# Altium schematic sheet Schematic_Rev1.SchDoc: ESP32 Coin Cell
size Letter; DrawnBy: x; Engineer: x; Address1: Mike Rankin; Address2: 0miker0@gmail.com; Address3: @mikerankin; DocumentNumber: 1; Revision: 1; SheetNumber: 1; SheetTotal: 1
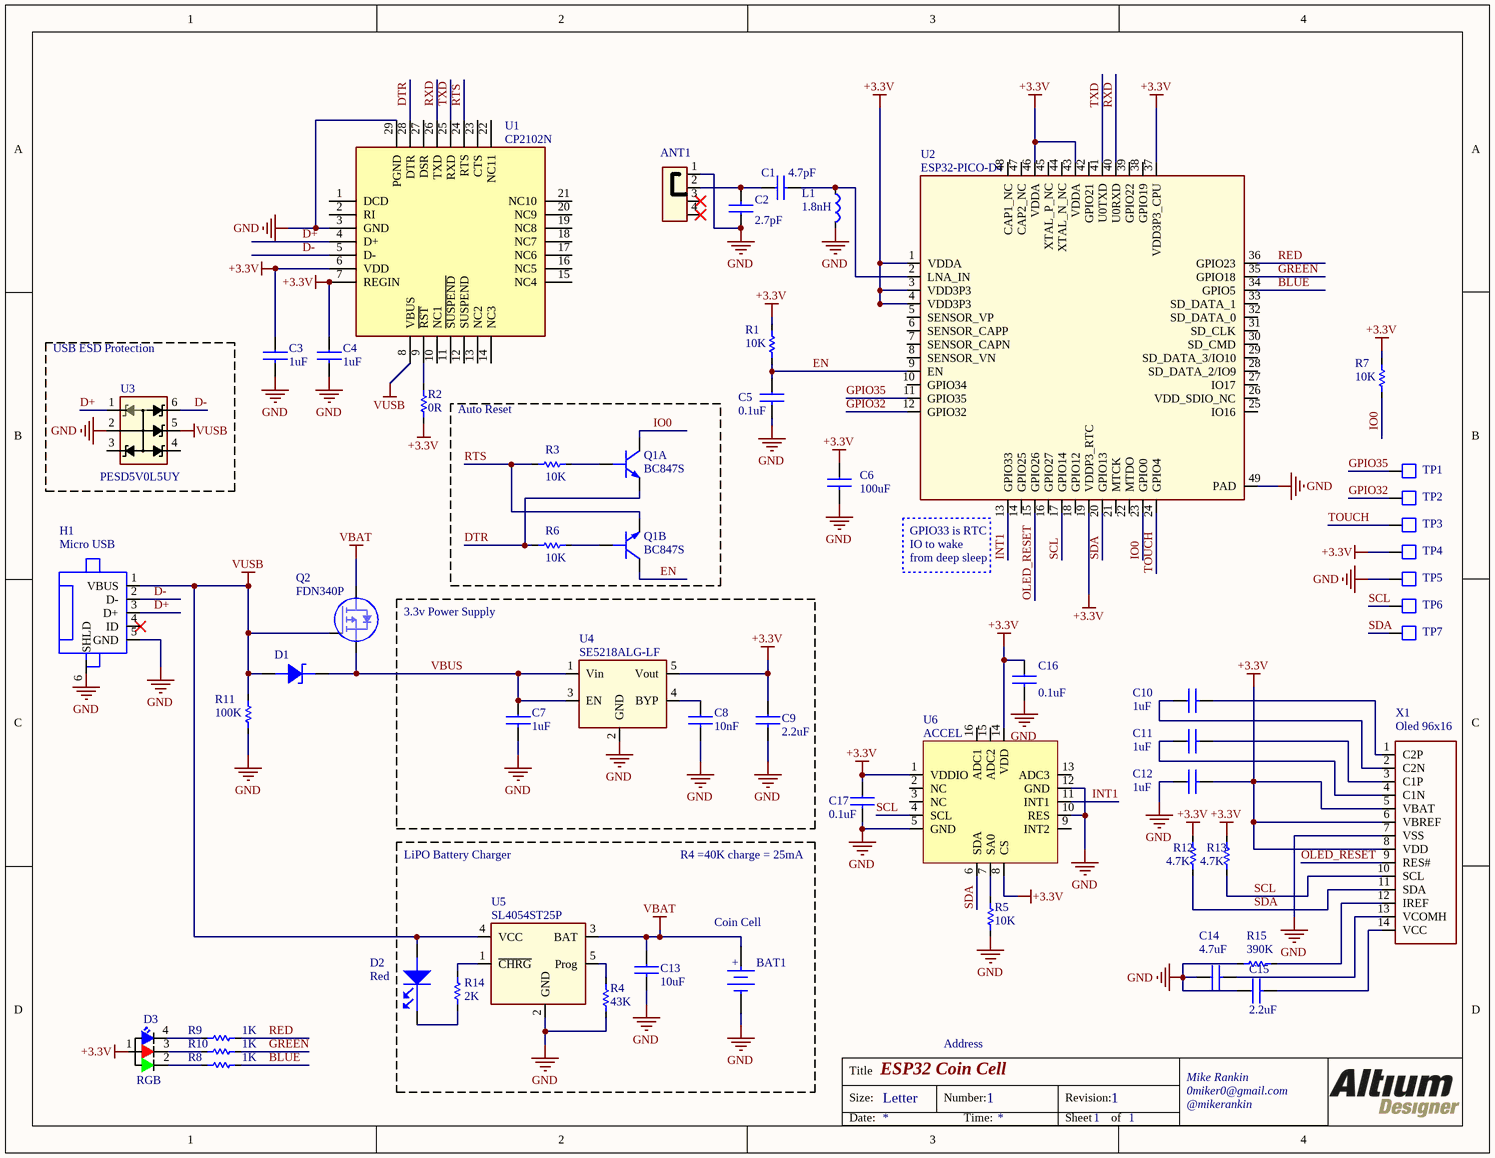
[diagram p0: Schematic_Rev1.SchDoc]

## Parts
ANT1  RF ANT 2.4GHZ STAMPED MET SLD  [PRO-OB-440]  (value not drawn)
BAT1  BATTERY-HOLDER (2450)  [BU2450SM-JJ-GTR]  (value not drawn)
C1  4.7pF  [CAPC1005X56N]
C2  2.7pF  [CAPC1005X56N]
C3  1uF  [CAPC1005X56N]
C4  1uF  [CAPC1005X56N]
C5  0.1uF  [CAPC1005X56N]
C6  100uF  [CAPC3216X160N]
C7  1uF  [CAPC1005X56N]
C8  10nF  [CAPC1005X56N]
C9  2.2uF  [CAPC1005X56N]
C10  1uF  [CAPC1005X56N]
C11  1uF  [CAPC1005X56N]
C12  1uF  [CAPC1005X56N]
C13  10uF  [CAPC2012X140N]
C14  4.7uF  [CAPC1005X56N]
C15  2.2uF  [CAPC1005X56N]
C16  0.1uF  [RESC1005X40L]
C17  0.1uF  [CAPC1005X56N]
D1  MBR0520-TP  [SOD123]  (value not drawn)
D2  value Red  [LED1608X55N-RED]  (hidden comment: LED_0603)
D3  RGB  [FC-B1010RGBT-HG]
H1  Micro USB  [1981584-1]
L1  value 1.8nH  [RESC1005X40L]  (hidden comment: Inductor)
Q1  BC847S  [SOT65P210X110-6N]  (parts A,B of 2)
Q2  FDN340P  [SOT95P240X110-3N]
R1  10K  [RESC1005X40L]
R2  0R  [RESC1005X40L]
R3  10K  [RESC1005X40L]
R4  43K  [RESC1005X40L]
R5  10K  [RESC1005X40L]
R6  10K  [RESC1005X40L]
R7  10K  [RESC1005X40L]
R8  1K  [RESC1005X40L]
R9  1K  [RESC1005X40L]
R10  1K  [RESC1005X40L]
R11  100K  [RESC1005X40L]
R12  4.7K  [RESC1005X40L]
R13  4.7K  [RESC1005X40L]
R14  2K  [RESC1005X40L]
R15  390K  [RESC1005X40L]
TP1  Test Point, 1mm Top Layer  [TP100TL]  (value not drawn)  (no BOM)
TP2  Test Point, 1mm Top Layer  [TP100TL]  (value not drawn)  (no BOM)
TP3  Test Point, 1mm Top Layer  [TP100TL]  (value not drawn)  (no BOM)
TP4  Test Point, 1mm Top Layer  [TP100TL]  (value not drawn)  (no BOM)
TP5  Test Point, 1mm Top Layer  [TP100TL]  (value not drawn)  (no BOM)
TP6  Test Point, 1mm Top Layer  [TP100TL]  (value not drawn)  (no BOM)
TP7  Test Point, 1mm Top Layer  [TP100TL]  (value not drawn)  (no BOM)
U1  CP2102N  [28-QFN]
U2  ESP32-PICO-D4  [QFN48]
U3  PESD5V0L5UY  [SOT65P210X110-6N]
U4  SE5218ALG-LF  [SOT95P280X144-5N]
U5  SL4054ST25P  [SOT95P280X144-5N]
U6  ACCEL  [QFN3X3_16_1.2]
X1  OLED_GLASS 96x16  [OLED_GLASS 96x16]  (value not drawn)

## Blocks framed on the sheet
USB ESD Protection: U3
Auto Reset: Q1 R3 R6
3.3v Power Supply: C7-C9 U4

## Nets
+3.3V: C3.1 C4.1 C6.1 C9.1 C12.2 C16.1 C17.1 D3.1 R1.1 R2.1 R7.1 R12.1 R13.1 TP4.1 U1.6(VDD) U1.7(REGIN) U2.1(VDDA) U2.3(VDD3P3) U2.4(VDD3P3) U2.19(VDDP3_RTC) U2.37(VDD3P3_CPU) U2.43(VDDA) U2.46(VDDA) U4.5(Vout) U6.1(VDDIO) U6.8(CS) U6.14(VDD) X1.5(VBAT) X1.6(VBREF) X1.8(VDD)
GND: ANT1.1 BAT1.2(-) C2.1 C3.2 C4.2 C5.2 C6.2 C7.2 C8.2 C9.2 C12.1 C13.2 C14.1 C15.1 C16.2 C17.2 H1.5(GND) H1.6(SHLD) L1.2 R4.2 R5.2 R11.2 R15.1 TP5.1 U1.3(GND) U1.29(PGND) U2.49(PAD) U3.2 U4.2(GND) U5.2(GND) U6.5(GND) U6.10(RES) U6.12(GND) X1.7(VSS)
VBAT: BAT1.1(+) C13.1 Q2.3(D) U5.3(BAT)
VUSB: D1.2(Annode) D2.2(ANODE) H1.1(VBUS) Q2.1(G) R11.1 U1.8(VBUS) U3.5 U5.4(VCC)
BLUE: R8.2 U2.34(GPIO5)
D+: H1.3(D+) U1.4(D+) U3.1
D-: H1.2(D-) U1.5(D-) U3.6
DTR: Q1.1(E1) R6.2 U1.28(DTR)
EN: C5.1 Q1.3(C2) R1.2 U2.9(EN)
GPIO32: TP2.1 U2.12(GPIO32)
GPIO35: TP1.1 U2.11(GPIO35)
GREEN: R10.2 U2.35(GPIO18)
INT1: U2.13(GPIO33) U6.11(INT1)
IO0: Q1.6(C1) R7.2 U2.23(GPIO0)
OLED_RESET: U2.15(GPIO26) X1.9(RES#)
RED: R9.2 U2.36(GPIO23)
RTS: Q1.4(E2) R3.2 U1.24(RTS)
RXD: U1.26(TXD) U2.40(U0RXD)
SCL: R13.2 TP6.1 U2.17(GPIO14) U6.4(SCL) X1.10(SCL)
SDA: R12.2 TP7.1 U2.20(GPIO13) U6.6(SDA) X1.11(SDA)
TOUCH: TP3.1 U2.24(GPIO4)
TXD: U1.25(RXD) U2.41(U0TXD)
VBUS: C7.1 D1.1(Cathode) Q2.2(S) U4.1(Vin) U4.3(EN)
NetANT1_2: ANT1.2 C1.1 C2.2
NetC1_2: C1.2 L1.1 U2.2(LNA_IN)
NetC8_1: C8.1 U4.4(BYP)
NetC10_1: C10.1 X1.2(C2N)
NetC10_2: C10.2 X1.1(C2P)
NetC11_1: C11.1 X1.4(C1N)
NetC11_2: C11.2 X1.3(C1P)
NetC14_2: C14.2 X1.13(VCOMH)
NetC15_2: C15.2 X1.14(VCC)
NetD2_1: D2.1(CATHODE) R14.1
NetD3_2: D3.2 R8.1
NetD3_3: D3.3 R10.1
NetD3_4: D3.4 R9.1
NetQ1_2: Q1.2(B1) R3.1
NetQ1_5: Q1.5(B2) R6.1
NetR2_2: R2.2 U1.9(~{RST})
NetR4_1: R4.1 U5.5(Prog)
NetR5_1: R5.1 U6.7(SA0)
NetR14_2: R14.2 U5.1(~{CHRG})
NetR15_2: R15.2 X1.12(IREF)

Not connected (* = marked no-connect by the designer): ANT1 3* 4*; H1 4(ID)*; U1 1(DCD) 2(RI) 10(NC1) 11(~{SUSPEND}) 12(SUSPEND) 13(NC2) 14(NC3) 15(NC4) 16(NC5) 17(NC6) 18(NC7) 19(NC8) 20(NC9) 21(NC10) 22(NC11) 23(CTS) 27(DSR); U2 5(SENSOR_VP) 6(SENSOR_CAPP) 7(SENSOR_CAPN) 8(SENSOR_VN) 10(GPIO34) 14(GPIO25) 16(GPIO27) 18(GPIO12) 21(MTCK) 22(MTDO) 25(IO16) 26(VDD_SDIO_NC) 27(IO17) 28(SD_DATA_2/IO9) 29(SD_DATA_3/IO10) 30(SD_CMD) 31(SD_CLK) 32(SD_DATA_0) 33(SD_DATA_1) 38(GPIO19) 39(GPIO22) 42(GPIO21) 44(XTAL_N_NC) 45(XTAL_P_NC) 47(CAP2_NC) 48(CAP1_NC); U3 3 4; U6 2(NC) 3(NC) 9(INT2) 13(ADC3) 15(ADC2) 16(ADC1)

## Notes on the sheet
- (near U2) GPIO33 is RTC
- (near U2) IO to wake
- (near U2) from deep sleep
- (near X1) Oled 96x16
- LiPO Battery Charger
- R4 =40K charge = 25mA
- (near BAT1) Coin Cell
- Address

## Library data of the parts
ANT1 = PRO-OB-440: Manufacturer: Proant AB; Vendor: Digi-Key
BAT1 = BU2450SM-JJ-GTR: HOLDER,BATT,COIN,24.5MM,SMT; Manufacturer: MPD; Value: Coin Cell Holder; Vendor: LCSC
C1 = CAP_0402: CAP CER 47pF 50V 0402; PartNumber: 0603N4R7C500CT; Manufacturer: Huaxin; Vendor: LCSC
C2 = CAP_0402: CAP CER 2.7pF 50V 0402; PartNumber: 0603N2R7C500; Manufacturer: Huaxin; Vendor: LCSC
C3 C4 C7 C10-C12 = CAP_0603: CAP CER 1uF 16V 0402; PartNumber: GRM155R61C105KA12D; Manufacturer: Murata; Vendor: LCSC
C5 C16 C17 = CAP_0402: CAP CER 0.1uF 16V 0402; PartNumber: TCC0402X5R104M160AT; Manufacturer: CCTC; Vendor: LCSC
C6 = CAP_1206: CAP CER 100uF 6.3V 1206; PartNumber: JMK316BJ107ML-T; Manufacturer: Taiyo Yuden; Vendor: LCSC
C8 = CAP_0603: CAP CER 10nF 0402; PartNumber: GRM155R71C103JA01D; Manufacturer: Murata; Vendor: LCSC
C9 = CAP_0402: CAP CER 2.2uF 16V 0402; Manufacturer: Samsung; PartNumber: CL05A225KO5NQNC; Vendor: LCSC
C13 = CAP_0805: CAP CER 10uF 16V 0805; PartNumber: CL21A106KOQNNNG; Manufacturer: Samsung; Vendor: LCSC
C14 = CAP_0603: CAP CER 4.7uF 16V 0402; PartNumber: CM05X5R475M16AH; Manufacturer: Kyocera; Vendor: LCSC
C15 = CAP_0402: CAP CER 2.2uF 16V 0402; PartNumber: CL05A225KO5NQNC; Manufacturer: Samsung; Vendor: LCSC
D1 = MBR0520-TP: DIODE SCHOTTKY 20V 500MA SOD123; Manufacturer: CJ; Vendor: LCSC
D2 = LED_0603: LED RED CLEAR 0603 SMD; Manufacturer: FNO; PartNumber: FC-DA1608HRK-620D; Vendor: LCSC
D3 = FC-B1010RGBT-HG: LED,RGB,SMD,RoHS; Manufacturer: Foshan; Vendor: LCSC
H1 = 1981584-1: CONN RCPT MICRO USB TYPE AB; Manufacturer: REG CON; PartNumber: C21377; Vendor: LCSC
L1 = Inductor: Inductor 1.8nH 0402; PartNumber: BKW0603UC1N8KGT; Manufacturer: GFBE; Vendor: LCSC
Q1 = BC847S: TRANS 2NPN 44V 0.1A SC-70-6; Manufacturer: Changjiang; Vendor: LCSC
Q2 = FDN340P: MOSFET P-CH 20V 2A SOT-23; Manufacturer: On Semi; Vendor: LCSC; Value: Mosfet P-H
R1 R3 R6 R7 = RES_0402: RES SMD 10K OHM 0402; PartNumber: RC-02W1002FT; Manufacturer: Guangdong; Vendor: LCSC
R2 = RES_0603: RES SMD 0R OHM 0402; Manufacturer: Yageo; PartNumber: RC0402JR-070RL; Vendor: LCSC
R4 = RES_0603: RES SMD 43K OHM 0402; Manufacturer: Uniroyal; PartNumber: 0402WGF4302TCE; Vendor: LCSC
R5 = RES_0603: RES SMD 10K OHM 0402; Manufacturer: Guangdong; PartNumber: RC-02W1002FT; Vendor: LCSC
R8-R10 = RES_0402: RES SMD 1K OHM 0402; PartNumber: RC0402FR-071KL; Manufacturer: Yageo; Vendor: LCSC
R11 = RES_0603: RES SMD 100K OHM 0402; Manufacturer: Uniroyal Elec; PartNumber: 0402WGF1003TCE; Vendor: LCSC
R12 = RES_0603: RES SMD 4.7K OHM 0402; Manufacturer: TA-I Tech; PartNumber: RM04FTN4701; Vendor: LCSC
R13 = RES_0603: RES SMD 4.7K OHM 0402; Manufacturer: HK Resistors; PartNumber: RM04FTN4701; Vendor: LCSC
R14 = RES_0603: RES SMD 2K OHM 1% 1/10W 0402; Manufacturer: LIZ Elec; PartNumber: CR0402FF2001G; Vendor: LCSC
R15 = RES_0603: RES SMD 390K OHM 0402; Manufacturer: Guangdong; PartNumber: RC-02W3903FT; Vendor: LCSC
U1 = CP2102N: IC BRIDGE USB TO UART 28QFN; Manufacturer: Silicon Labs; PartNumber: CP2102N-A01-GQFN28; Vendor: LCSC
U2 = ESP32-PICO-D4: RF Transceiver ICs QFN-48_7x7x05P RoHS; Manufacturer: Espressif; Vendor: LCSC
U3 = PESD5V0L5UY: TVS SOT-363 RoHS; Manufacturer: Yenji; Vendor: LCSC
U4 = SE5218ALG-LF: IC REG LDO 3.3V 0.5A SOT23-5; Manufacturer: Seaward; Vendor: LCSC
U5 = SL4054ST25P: Charger IC Lithium-Ion/Polymer SOT23-5; Manufacturer: Techfuse; Vendor: LCSC
U6 = E-05-177: IC ACCEL 2-16G I2C/SPI 16LGA; PartNumber: LIS3DHTR; Manufacturer: STMicro; Vendor: LCSC; Value: LIS3DHTR
X1 = OLED_GLASS 96x16: 96x16 OLED_GLASS; PartNumber: ER-OLED0.69-1W; Vendor: Buy-Display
